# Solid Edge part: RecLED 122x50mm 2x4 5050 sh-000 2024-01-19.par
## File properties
Author: jaroslaw.przewlocki
Template: iso metric part.par
Last saved by: jaroslaw.przewlocki
Revision: 2
Application: Solid Edge
Gęstość: 0,000 kg/m^3
Dokładność: 0,990
Username: jaroslaw.przewlocki
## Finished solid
Body 1: solid body, 957 faces, 2427 edges, 1526 vertices.
  Faces by surface: plane 439, cylinder 255, torus 104, cone 88, spline 51, sphere 20
  Edges by curve: line 1192, curve on surface 677, circle 266, spline 160, ellipse 132
Bounding box of the edges (mm; curved faces can reach further): 49.500 x 4.950 x 121.400, from (-24.75, -3.45, -60.7) to (24.75, 1.5, 60.7).
Cylindrical faces by radius (mm): R0.199 x2, R0.2 x78, R0.2002 x4, R0.2169 x6, R0.25 x24, R0.3 x4, R0.3373 x6, R0.4 x16, R0.4006 x4, R0.4008 x4, R0.525 x4, R0.6 x24, R1 x14, R1.05 x8, R1.0894 x4, R1.0991 x8, R1.1 x28, R1.5342 x3, R1.5343 x1, R1.7456 x1, R1.75 x2, R3.7549 x1, R5.3685 x1, R5.3987 x1, R5.4728 x1, R5.8982 x1, R7.5931 x1, R7.8648 x1, R8.5931 x1, R10.3711 x1, R11.964 x1
Conical faces (half-angle, radius in mm at the cone's reference point): 0.3913 deg R1.0968 x4, 0.447 deg R1.0952 x4, 0.464 deg R1.0955 x4, 0.5 deg R0.5056 x8, 0.5 deg R1.0082 x8, 1 deg R0.5511 x4, 10 deg R0.2132 x4, 10 deg R0.4132 x4, 15.6748 deg R1.1041 x2, 15.6751 deg R1.1041 x2, 15.7937 deg R1.1267 x2, 15.7938 deg R1.1267 x2, 18.4844 deg R1.0657 x8, 18.9316 deg R0.5099 x4, 19.4337 deg R0.5111 x4, 27.363 deg R0.6214 x4, 40.1968 deg R0.519 x2, 40.228 deg R0.5176 x2, 42.9179 deg R0.4919 x2, 42.9331 deg R0.4916 x2, 45 deg R0.575 x4, 45 deg R0.625 x8
Toroidal faces (ring radius, tube radius in mm): R0.0958 r0.3997 x8, R0.1 r0.2 x2, R0.1075 r0.4 x4, R0.1101 r0.4001 x4, R0.1216 r0.4 x4, R0.1234 r0.4 x4, R0.1634 r0.2287 x2, R0.1641 r0.2287 x2, R0.3286 r0.2001 x2, R0.3702 r0.4 x4, R0.3818 r0.2 x4, R0.4163 r0.3984 x4, R0.4824 r0.2001 x2, R0.4952 r0.2 x2, R0.6008 r0.3968 x4, R0.6009 r0.3969 x4, R0.6227 r0.2 x2, R0.6235 r0.2 x2, R0.8 r0.2 x8, R0.8522 r0.3 x4, R0.9002 r0.2 x2, R0.9018 r0.2 x2, R0.9181 r0.2227 x4, R0.9197 r0.223 x2, R0.9199 r0.223 x2, R0.9663 r0.2263 x2, R0.9665 r0.2263 x2, R1.3 r0.2 x4, R1.327 r1.1 x4, R1.3271 r1.1 x4, R1.8741 r0.2175 x2, R1.8987 r0.2 x2
Spherical faces by radius (mm): R0.2 x16, R0.6 x4
Planar faces by outward normal: +x 41, +y 15, +z 37, -x 41, -y 65, -z 56, oblique 184
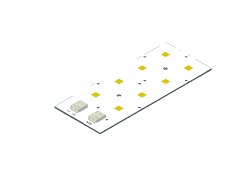
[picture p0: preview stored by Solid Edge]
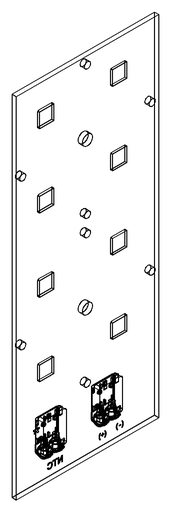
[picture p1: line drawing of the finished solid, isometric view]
